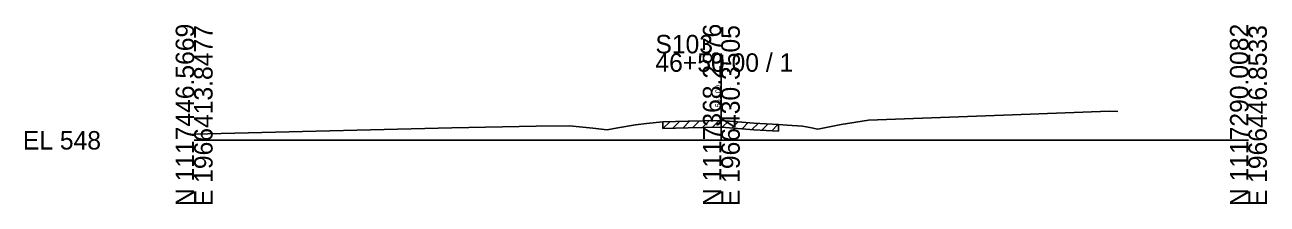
# Model space of a CAD drawing. Extents: x -26 to 163, y -10 to 45020.
# Drawn here: x -25.7 to 162.8, y 6490.3 to 6517.5 of the extents above; entities that cross this region are included whole.
import ezdxf

# ---------------------------------------------------------------- set-up
doc = ezdxf.new("R2010")
doc.units = 0
for name, color, linetype in [('RD_GPK_XS_Cell', 7, 'Continuous'), ('RD_XS_ExGround', 7, 'Continuous'), ('RD_XS_ExPaveRet', 7, 'Continuous'), ('RD_XS_TX_Elev_EX', 7, 'Continuous')]:
    doc.layers.add(name, color=color, linetype=linetype)

msp = doc.modelspace()

# ---------------------------------------------------------------- linework, layer by layer
at = {"layer": 'RD_GPK_XS_Cell'}
for p, q in [((80, 6500), (80, 6513.2)), ((0, 6500), (80, 6500)), ((80, 6500), (160, 6500))]:
    msp.add_line(p, q, dxfattribs=at)
at = {"layer": 'RD_XS_ExGround'}
for p, q in [((124.17, 6503.85), (138.87, 6504.4)), ((138.87, 6504.4), (140.19, 6504.36)), ((66.96, 6502.36), (68.66, 6502.54)), ((68.66, 6502.54), (71.15, 6502.78)), ((71.15, 6502.78), (74.95, 6502.89)), ((74.95, 6502.89), (80.01, 6503)), ((80.01, 6503), (84.95, 6502.61)), ((84.95, 6502.61), (88.67, 6502.38)), ((98.17, 6502.4), (102.32, 6503.07)), ((102.32, 6503.07), (124.17, 6503.85)), ((0, 6500.93), (39.09, 6501.87)), ((39.09, 6501.87), (51.93, 6502.17)), ((51.93, 6502.17), (56.96, 6502.22)), ((56.96, 6502.22), (60.52, 6501.85)), ((60.52, 6501.85), (62.7, 6501.59)), ((62.7, 6501.59), (64.32, 6501.87)), ((64.32, 6501.87), (66.96, 6502.36)), ((88.67, 6502.38), (90.01, 6502.29)), ((90.01, 6502.29), (92.31, 6502.17)), ((92.31, 6502.17), (93.43, 6501.94)), ((93.43, 6501.94), (94.65, 6501.7)), ((94.65, 6501.7), (98.17, 6502.4))]:
    msp.add_line(p, q, dxfattribs=at)
at = {"layer": 'RD_XS_ExPaveRet'}
for p, q in [((71.15, 6501.78), (72.18, 6502.81)), ((71.15, 6501.78), (71.15, 6502.78)), ((72.65, 6501.82), (73.68, 6502.85)), ((74.15, 6501.86), (75.18, 6502.89)), ((75.65, 6501.9), (76.67, 6502.93)), ((77.15, 6501.94), (78.17, 6502.96)), ((78.65, 6501.97), (79.67, 6502.99)), ((80.15, 6501.99), (81.08, 6502.92)), ((81.65, 6501.87), (82.58, 6502.8)), ((83.15, 6501.75), (84.08, 6502.68)), ((84.65, 6501.63), (85.59, 6502.57)), ((71.15, 6501.78), (74.95, 6501.89)), ((74.95, 6501.89), (80.01, 6502)), ((80.01, 6502), (84.95, 6501.61)), ((84.95, 6501.61), (88.67, 6501.38)), ((86.15, 6501.54), (87.09, 6502.48)), ((87.65, 6501.44), (88.59, 6502.38)), ((88.67, 6502.38), (88.67, 6501.38))]:
    msp.add_line(p, q, dxfattribs=at)

# ---------------------------------------------------------------- texts
at = {"layer": 'RD_GPK_XS_Cell'}
for s, p in [('N 1117446.5669', (0, 6490)), ('E 1966413.8477', (2.8, 6490)), ('N 1117368.2876', (80, 6490)), ('E 1966430.3505', (82.8, 6490)), ('N 1117290.0082', (160, 6490)), ('E 1966446.8533', (162.8, 6490))]:
    msp.add_text(s, height=2.8, rotation=90, dxfattribs=at).set_placement(p)
for s, p in [('S103', (70, 6513.2)), ('46+50.00 / 1', (70, 6510.4)), ('EL 548', (-26, 6498.6))]:
    msp.add_text(s, height=2.8, dxfattribs=at).set_placement(p)
at = {"layer": 'RD_XS_TX_Elev_EX'}
msp.add_text('551.00', height=0.8, rotation=90, dxfattribs=at).set_placement((79.9, 6505))

doc.saveas('drawing.dxf')
